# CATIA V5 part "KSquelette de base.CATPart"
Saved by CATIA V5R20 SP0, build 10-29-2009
Part number: K_Squelette de base
Property "hauteur_axe": 190 mm
Property "hauteur_coulisso": 570 mm
Property "diamemtre_vilebrequin": 100 mm
Bounding box of the stored display mesh (mm): x 0 to 0, y 125 to 160, z 190 to 570
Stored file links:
  C:\Users\thinkmotion1\Desktop\Khaled_IAO_Pack2\IAO_2010_1392_rragonneau\CATIA_1392_rragonneau\KSquelette de base.CATPart
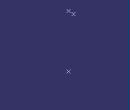
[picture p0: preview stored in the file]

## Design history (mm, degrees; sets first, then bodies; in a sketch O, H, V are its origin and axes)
Parameters
  position_coulisso = 35 mm
  hauteur_axe = 90 mm
  hauteur_coulisso = 170 mm
  diametre_vilebrequin = 100 mm
Point1: type OnPlane, Support yz-plane, H 125.927, V 190, Direction (0, 1, 0)
Point2: type OnPlane, Support yz-plane, H 90, V 231.307, Direction (0, 1, 0)
Set1
  Point3: type OnPlane, Support yz-plane, H 160 {= 125mm+position_coulisso}, V 570, Direction (0, 1, 0)
  Point4: type OnPlane, Support yz-plane, H 125, V 570, Direction (0, 1, 0)
Body1 (main body)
